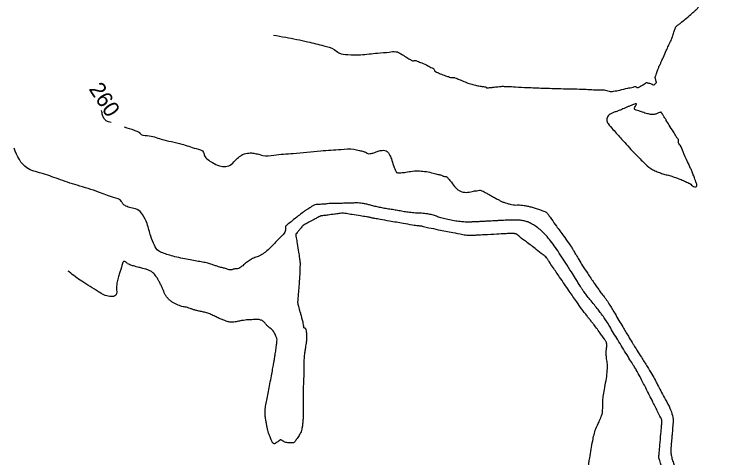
# Model space of a CAD drawing. Extents: x -478102 to -473059, y -1117705 to -1114104.
# Drawn here: x -475265.5 to -475088.2, y -1116409 to -1116297 of the extents above; entities that cross this region are included whole.
import ezdxf

# ---------------------------------------------------------------- set-up
doc = ezdxf.new("R2010")
doc.units = 0
for name, color, linetype in [('Vrstevnice_hlavni', 7, 'Continuous'), ('Vrstevnice_popis', 7, 'Continuous'), ('Vrstevnice_vedlejsi', 7, 'Continuous')]:
    doc.layers.add(name, color=color, linetype=linetype)

msp = doc.modelspace()

# ---------------------------------------------------------------- linework, layer by layer
at = {"layer": 'Vrstevnice_hlavni'}
for points in [[(-475240.975, -1116324.335), (-475242.24, -1116323.875), (-475242.75, -1116323.343), (-475243.137, -1116322.506), (-475243.415, -1116321.305)], [(-475237.687, -1116325.457), (-475235.201, -1116326.249), (-475234.334, -1116326.581), (-475233.844, -1116326.849), (-475233.73, -1116327.052), (-475231.91, -1116327.609), (-475228.384, -1116328.517), (-475223.153, -1116329.779), (-475219.586, -1116330.906), (-475217.681, -1116331.898), (-475217.44, -1116332.755), (-475216.694, -1116333.605), (-475215.441, -1116334.448), (-475213.683, -1116335.283), (-475212.092, -1116335.422), (-475210.667, -1116334.864), (-475209.409, -1116333.609), (-475208.319, -1116332.727), (-475207.397, -1116332.218), (-475206.642, -1116332.081), (-475205.948, -1116332.022), (-475205.314, -1116332.042), (-475204.739, -1116332.139), (-475204.122, -1116332.27), (-475203.462, -1116332.435), (-475202.76, -1116332.635), (-475199.972, -1116332.541), (-475195.097, -1116332.152), (-475188.137, -1116331.469), (-475183.035, -1116331.113), (-475179.791, -1116331.083), (-475178.406, -1116331.38), (-475177.36, -1116331.658), (-475176.654, -1116331.916), (-475176.288, -1116332.154), (-475175.662, -1116332.174), (-475174.776, -1116331.975), (-475173.631, -1116331.557), (-475172.686, -1116331.362), (-475171.941, -1116331.391), (-475171.397, -1116331.643), (-475170.862, -1116332.357), (-475170.337, -1116333.533), (-475169.822, -1116335.172), (-475169.381, -1116336.301), (-475169.015, -1116336.92), (-475168.725, -1116337.029), (-475167.953, -1116337.013), (-475166.701, -1116336.871), (-475164.969, -1116336.603), (-475163.238, -1116336.553), (-475161.509, -1116336.722), (-475159.783, -1116337.108), (-475158.522, -1116337.413), (-475157.729, -1116337.635), (-475157.401, -1116337.776), (-475157.09, -1116337.883), (-475156.795, -1116337.957), (-475156.517, -1116337.998), (-475155.978, -1116338.488), (-475155.178, -1116339.429), (-475154.117, -1116340.82), (-475152.888, -1116341.664), (-475151.489, -1116341.961), (-475149.92, -1116341.711), (-475148.805, -1116341.537), (-475148.141, -1116341.439), (-475147.93, -1116341.416), (-475147.518, -1116341.551), (-475146.905, -1116341.845), (-475146.091, -1116342.298), (-475145.239, -1116342.772), (-475144.347, -1116343.269), (-475143.416, -1116343.787), (-475142.747, -1116344.148), (-475142.34, -1116344.352), (-475142.195, -1116344.4), (-475141.824, -1116344.514), (-475141.227, -1116344.693), (-475140.403, -1116344.939), (-475139.648, -1116345.093), (-475138.96, -1116345.154), (-475138.341, -1116345.124), (-475137.645, -1116345.157), (-475136.873, -1116345.252), (-475136.023, -1116345.411), (-475135.095, -1116345.637), (-475134.087, -1116345.929), (-475132.999, -1116346.289), (-475132.178, -1116346.581), (-475131.622, -1116346.805), (-475131.332, -1116346.962), (-475131.076, -1116347.169), (-475130.854, -1116347.427), (-475130.666, -1116347.736), (-475129.952, -1116348.756), (-475128.712, -1116350.487)], [(-475128.712, -1116350.487), (-475126.947, -1116352.929), (-475125.688, -1116354.692), (-475124.936, -1116355.774), (-475124.689, -1116356.176), (-475124.297, -1116356.837), (-475123.761, -1116357.756), (-475123.079, -1116358.935), (-475122.099, -1116360.499), (-475120.82, -1116362.449), (-475119.242, -1116364.785), (-475118.059, -1116366.501), (-475117.27, -1116367.598), (-475116.877, -1116368.076), (-475116.545, -1116368.489), (-475116.273, -1116368.839), (-475116.062, -1116369.125), (-475115.278, -1116370.396), (-475113.922, -1116372.653), (-475111.992, -1116375.896), (-475110.564, -1116378.288), (-475109.637, -1116379.83), (-475109.21, -1116380.521), (-475108.43, -1116381.767), (-475107.298, -1116383.569), (-475105.813, -1116385.925), (-475104.633, -1116387.876), (-475103.758, -1116389.422), (-475103.189, -1116390.563), (-475102.425, -1116392.024), (-475101.465, -1116393.806), (-475100.311, -1116395.909), (-475099.582, -1116397.851), (-475099.279, -1116399.632), (-475099.401, -1116401.253), (-475099.506, -1116402.6), (-475099.594, -1116403.675), (-475099.665, -1116404.478), (-475099.736, -1116405.304), (-475099.806, -1116406.152), (-475099.875, -1116407.025), (-475099.8, -1116408.005), (-475099.581, -1116409.094), (-475099.218, -1116410.291), (-475098.892, -1116411.377), (-475098.603, -1116412.354), (-475098.351, -1116413.22), (-475097.9, -1116414.106), (-475097.251, -1116415.011), (-475096.403, -1116415.935), (-475095.646, -1116416.751), (-475094.98, -1116417.459), (-475094.404, -1116418.058), (-475093.929, -1116418.639), (-475093.553, -1116419.201), (-475093.277, -1116419.744), (-475092.975, -1116420.422), (-475092.648, -1116421.234), (-475092.295, -1116422.179), (-475091.967, -1116423.198), (-475091.665, -1116424.289), (-475091.387, -1116425.454), (-475091.154, -1116426.436), (-475090.963, -1116427.235), (-475090.817, -1116427.851), (-475090.546, -1116428.687), (-475090.149, -1116429.742), (-475089.629, -1116431.015), (-475089.217, -1116431.994), (-475088.916, -1116432.677), (-475088.723, -1116433.065), (-475088.302, -1116433.641), (-475087.651, -1116434.404), (-475086.771, -1116435.354), (-475086.194, -1116436.127), (-475085.92, -1116436.721), (-475085.947, -1116437.137), (-475085.918, -1116437.46), (-475085.832, -1116437.689), (-475085.689, -1116437.825), (-475085.536, -1116437.999), (-475085.372, -1116438.211), (-475085.197, -1116438.461), (-475084.597, -1116439.5), (-475083.572, -1116441.328), (-475082.121, -1116443.945), (-475080.77, -1116446.086), (-475079.518, -1116447.752), (-475078.365, -1116448.942), (-475077.137, -1116450.177), (-475075.834, -1116451.457), (-475073.077, -1116454.108)]]:
    msp.add_spline(points, degree=3, dxfattribs=at)
at = {"layer": 'Vrstevnice_vedlejsi'}
for points in [[(-475152.721, -1116313.661), (-475151.357, -1116314.246), (-475150.061, -1116314.693), (-475148.833, -1116315.001), (-475147.674, -1116315.17), (-475146.877, -1116315.315), (-475146.443, -1116315.435), (-475146.371, -1116315.529), (-475146.287, -1116315.587), (-475146.192, -1116315.607), (-475146.085, -1116315.59), (-475145.596, -1116315.533), (-475144.725, -1116315.437), (-475143.473, -1116315.301), (-475142.637, -1116315.211), (-475142.219, -1116315.166), (-475142.218, -1116315.166), (-475142.206, -1116315.17), (-475142.182, -1116315.178), (-475142.147, -1116315.19), (-475141.105, -1116315.248), (-475139.057, -1116315.354), (-475136.002, -1116315.506), (-475132.173, -1116315.649), (-475127.57, -1116315.784), (-475122.193, -1116315.91), (-475118.375, -1116316.064), (-475116.116, -1116316.247), (-475115.416, -1116316.458), (-475114.287, -1116316.433), (-475112.73, -1116316.171), (-475110.744, -1116315.673), (-475109.364, -1116315.398), (-475108.59, -1116315.346), (-475108.421, -1116315.516), (-475108.063, -1116315.468), (-475107.515, -1116315.202), (-475106.778, -1116314.719), (-475106.277, -1116314.398), (-475106.012, -1116314.238), (-475105.982, -1116314.241), (-475105.807, -1116314.286), (-475105.487, -1116314.376), (-475105.022, -1116314.509), (-475104.68, -1116314.635), (-475104.461, -1116314.755), (-475104.365, -1116314.869), (-475104.212, -1116314.865), (-475103.999, -1116314.744), (-475103.728, -1116314.505), (-475103.554, -1116314.331), (-475103.475, -1116314.222), (-475103.493, -1116314.177), (-475103.536, -1116314.024), (-475103.603, -1116313.762), (-475103.694, -1116313.392), (-475103.761, -1116313.134), (-475103.803, -1116312.989), (-475103.821, -1116312.956), (-475103.714, -1116312.609), (-475103.481, -1116311.95), (-475103.123, -1116310.977), (-475102.854, -1116310.276), (-475102.675, -1116309.845), (-475102.585, -1116309.685), (-475102.277, -1116309.02), (-475101.752, -1116307.85), (-475101.01, -1116306.174), (-475100.456, -1116304.958), (-475100.09, -1116304.201), (-475099.912, -1116303.903), (-475099.679, -1116303.318), (-475099.391, -1116302.445), (-475099.048, -1116301.284), (-475098.705, -1116300.441), (-475098.363, -1116299.917), (-475098.023, -1116299.71), (-475097.315, -1116299.162), (-475096.242, -1116298.274), (-475094.802, -1116297.044), (-475093.807, -1116296.183), (-475093.256, -1116295.69), (-475093.149, -1116295.565), (-475092.996, -1116295.294), (-475092.795, -1116294.877), (-475092.547, -1116294.315), (-475092.28, -1116293.874), (-475091.993, -1116293.556), (-475091.686, -1116293.36), (-475091.142, -1116293.181), (-475090.361, -1116293.019), (-475089.343, -1116292.873), (-475088.364, -1116292.639), (-475087.426, -1116292.318), (-475086.526, -1116291.909), (-475085.548, -1116291.453), (-475084.49, -1116290.949)], [(-475200.063, -1116302.278), (-475196.986, -1116302.839), (-475191.444, -1116303.945), (-475187.356, -1116304.971), (-475184.723, -1116305.915), (-475183.543, -1116306.779), (-475181.332, -1116307.215), (-475178.09, -1116307.223), (-475173.817, -1116306.804), (-475170.847, -1116306.551), (-475169.18, -1116306.463), (-475168.816, -1116306.541), (-475168.19, -1116306.843), (-475167.302, -1116307.368), (-475166.152, -1116308.116), (-475165.299, -1116308.583), (-475164.742, -1116308.77), (-475164.482, -1116308.675), (-475163.793, -1116308.85), (-475162.676, -1116309.296), (-475161.129, -1116310.012), (-475160.07, -1116310.578), (-475159.499, -1116310.995), (-475159.415, -1116311.262), (-475158.914, -1116311.607), (-475157.997, -1116312.03), (-475156.662, -1116312.532), (-475155.703, -1116312.855), (-475155.12, -1116313.001), (-475154.913, -1116312.969), (-475154.705, -1116312.963), (-475154.498, -1116312.983), (-475154.292, -1116313.03), (-475153.699, -1116313.256), (-475152.721, -1116313.661)], [(-475097.965, -1116328.589), (-475097.927, -1116328.981), (-475097.916, -1116329.121), (-475097.912, -1116329.205), (-475097.916, -1116329.233), (-475097.537, -1116330.084), (-475096.776, -1116331.757), (-475095.633, -1116334.251), (-475094.868, -1116335.923), (-475094.48, -1116336.771), (-475094.47, -1116336.797), (-475094.283, -1116337.295), (-475093.921, -1116338.265), (-475093.383, -1116339.709), (-475093.356, -1116340.466), (-475093.841, -1116340.538), (-475094.838, -1116339.924), (-475095.888, -1116339.363), (-475096.99, -1116338.856), (-475098.144, -1116338.403), (-475099.301, -1116338.002), (-475100.461, -1116337.651), (-475101.624, -1116337.351), (-475102.755, -1116336.968), (-475103.856, -1116336.5), (-475104.925, -1116335.949), (-475106.684, -1116334.435), (-475109.132, -1116331.959), (-475112.269, -1116328.522), (-475114.452, -1116326.075), (-475115.681, -1116324.618), (-475115.956, -1116324.153), (-475116.041, -1116323.672), (-475115.937, -1116323.177), (-475115.643, -1116322.668), (-475115.172, -1116322.236), (-475114.523, -1116321.881), (-475113.696, -1116321.603), (-475112.936, -1116321.324), (-475112.243, -1116321.044), (-475111.617, -1116320.763), (-475110.956, -1116320.478), (-475110.26, -1116320.187), (-475109.529, -1116319.892), (-475108.995, -1116319.692), (-475108.657, -1116319.588), (-475108.517, -1116319.58), (-475108.518, -1116319.724), (-475108.659, -1116320.019), (-475108.942, -1116320.467), (-475109.023, -1116320.812), (-475108.902, -1116321.054), (-475108.581, -1116321.193), (-475107.952, -1116321.417), (-475107.017, -1116321.727), (-475105.773, -1116322.123), (-475104.717, -1116322.301), (-475103.848, -1116322.261), (-475103.166, -1116322.002), (-475102.695, -1116321.817), (-475102.435, -1116321.704), (-475102.386, -1116321.664), (-475102.266, -1116321.788), (-475102.076, -1116322.074), (-475101.814, -1116322.523), (-475101.628, -1116322.845), (-475101.517, -1116323.039), (-475101.481, -1116323.106), (-475101.453, -1116323.152), (-475101.434, -1116323.178), (-475101.423, -1116323.185), (-475101.409, -1116323.194), (-475101.391, -1116323.208), (-475101.37, -1116323.225), (-475101, -1116323.81), (-475100.281, -1116324.963), (-475099.214, -1116326.685), (-475098.487, -1116327.847), (-475098.102, -1116328.449), (-475098.058, -1116328.492), (-475098.023, -1116328.526), (-475097.997, -1116328.552), (-475097.965, -1116328.589)], [(-475158.731, -1116348.111), (-475159.722, -1116347.73), (-475160.912, -1116347.451), (-475162.3, -1116347.275), (-475163.886, -1116347.201), (-475165.382, -1116347.074), (-475166.785, -1116346.895), (-475168.098, -1116346.663), (-475169.415, -1116346.436), (-475170.735, -1116346.214), (-475172.06, -1116345.996), (-475173.309, -1116345.754), (-475174.481, -1116345.488), (-475175.577, -1116345.197), (-475176.528, -1116344.968), (-475177.333, -1116344.801), (-475177.993, -1116344.696), (-475178.759, -1116344.641), (-475179.63, -1116344.636), (-475180.606, -1116344.682), (-475181.738, -1116344.715), (-475183.026, -1116344.736), (-475184.47, -1116344.745), (-475185.607, -1116344.776), (-475186.437, -1116344.827), (-475186.96, -1116344.9), (-475187.554, -1116344.953), (-475188.219, -1116344.986), (-475188.954, -1116344.999), (-475189.644, -1116345.147), (-475190.288, -1116345.431), (-475190.886, -1116345.85), (-475191.368, -1116346.174), (-475191.735, -1116346.403), (-475191.986, -1116346.536), (-475192.676, -1116347.039), (-475193.804, -1116347.91), (-475195.37, -1116349.15), (-475196.425, -1116349.99), (-475196.969, -1116350.431), (-475197.002, -1116350.471), (-475197.026, -1116350.667), (-475197.041, -1116351.02), (-475197.047, -1116351.53), (-475197.212, -1116352.028), (-475197.537, -1116352.515), (-475198.022, -1116352.991), (-475198.781, -1116353.764), (-475199.814, -1116354.835), (-475201.12, -1116356.204), (-475202.383, -1116357.259), (-475203.601, -1116357.999), (-475204.774, -1116358.424), (-475205.87, -1116358.977), (-475206.887, -1116359.66), (-475207.826, -1116360.471), (-475208.565, -1116361.005), (-475209.105, -1116361.262), (-475209.445, -1116361.241), (-475209.807, -1116361.275), (-475210.191, -1116361.363), (-475210.596, -1116361.506), (-475211.022, -1116361.538), (-475211.468, -1116361.459), (-475211.935, -1116361.269), (-475212.4, -1116361.113), (-475212.862, -1116360.991), (-475213.322, -1116360.903), (-475213.925, -1116360.731), (-475214.671, -1116360.473), (-475215.56, -1116360.132), (-475216.647, -1116359.827), (-475217.932, -1116359.56), (-475219.414, -1116359.329), (-475221.073, -1116359.024), (-475222.906, -1116358.645), (-475224.916, -1116358.191), (-475226.611, -1116357.719), (-475227.992, -1116357.23), (-475229.059, -1116356.723), (-475230.069, -1116355.322), (-475231.023, -1116353.029), (-475231.919, -1116349.842), (-475233.058, -1116347.587), (-475234.439, -1116346.264), (-475236.062, -1116345.872), (-475237.26, -1116345.405), (-475238.033, -1116344.861), (-475238.381, -1116344.242), (-475240.418, -1116343.253), (-475244.143, -1116341.897), (-475249.556, -1116340.172), (-475254.377, -1116338.582), (-475258.605, -1116337.127), (-475262.24, -1116335.808), (-475265.477, -1116330.842)], [(-475188.022, -1116347.916), (-475188.118, -1116347.918), (-475188.207, -1116347.937), (-475188.291, -1116347.974), (-475188.368, -1116348.028), (-475188.867, -1116348.302), (-475189.787, -1116348.796), (-475191.128, -1116349.509), (-475192.049, -1116350.005), (-475192.55, -1116350.286), (-475192.631, -1116350.35), (-475192.879, -1116350.629), (-475193.293, -1116351.123), (-475193.874, -1116351.832), (-475194.261, -1116352.309), (-475194.455, -1116352.554), (-475194.455, -1116352.568), (-475194.455, -1116352.589), (-475194.453, -1116352.616), (-475194.451, -1116352.65), (-475194.331, -1116353.402), (-475194.093, -1116354.873), (-475193.737, -1116357.062), (-475193.497, -1116358.62), (-475193.374, -1116359.547), (-475193.367, -1116359.843), (-475193.372, -1116360.37), (-475193.389, -1116361.128), (-475193.417, -1116362.116), (-475193.49, -1116363.448), (-475193.608, -1116365.123), (-475193.772, -1116367.141), (-475193.887, -1116368.581), (-475193.953, -1116369.442), (-475193.97, -1116369.725), (-475193.915, -1116370.149), (-475193.789, -1116370.715), (-475193.592, -1116371.423), (-475193.46, -1116371.896), (-475193.394, -1116372.135), (-475193.393, -1116372.139), (-475193.375, -1116372.184), (-475193.34, -1116372.269), (-475193.288, -1116372.395), (-475193.163, -1116372.836), (-475192.966, -1116373.594), (-475192.696, -1116374.668), (-475192.535, -1116375.417), (-475192.484, -1116375.841), (-475192.542, -1116375.94), (-475192.497, -1116376.03), (-475192.351, -1116376.11), (-475192.102, -1116376.181), (-475191.916, -1116376.537), (-475191.791, -1116377.179), (-475191.729, -1116378.108), (-475191.717, -1116378.896), (-475191.757, -1116379.544), (-475191.847, -1116380.052), (-475191.959, -1116380.768), (-475192.094, -1116381.693), (-475192.252, -1116382.826), (-475192.352, -1116383.918), (-475192.394, -1116384.97), (-475192.379, -1116385.98), (-475192.394, -1116387.165), (-475192.438, -1116388.525), (-475192.511, -1116390.058), (-475192.559, -1116391.582), (-475192.582, -1116393.096), (-475192.579, -1116394.6), (-475192.576, -1116395.902), (-475192.573, -1116397.002), (-475192.569, -1116397.901), (-475192.601, -1116398.849), (-475192.669, -1116399.846), (-475192.774, -1116400.892), (-475192.918, -1116401.742), (-475193.101, -1116402.397), (-475193.325, -1116402.857), (-475193.6, -1116403.337), (-475193.927, -1116403.838), (-475194.305, -1116404.359), (-475194.59, -1116404.741), (-475194.781, -1116404.983), (-475194.879, -1116405.086), (-475195.149, -1116405.151), (-475195.592, -1116405.177), (-475196.208, -1116405.165), (-475196.732, -1116405.095), (-475197.166, -1116404.967), (-475197.509, -1116404.782), (-475197.765, -1116404.64), (-475197.936, -1116404.543), (-475198.021, -1116404.489), (-475198.122, -1116404.455), (-475198.237, -1116404.44)], [(-475121.059, -1116414.567), (-475120.318, -1116408.958), (-475119.556, -1116404.64), (-475118.772, -1116401.612), (-475117.966, -1116399.876), (-475117.414, -1116398.553), (-475117.116, -1116397.642), (-475117.072, -1116397.145), (-475117.038, -1116396.462), (-475117.013, -1116395.595), (-475116.998, -1116394.542), (-475116.841, -1116393.075), (-475116.543, -1116391.194), (-475116.104, -1116388.899), (-475115.876, -1116386.929), (-475115.86, -1116385.286), (-475116.056, -1116383.969), (-475116.148, -1116382.808), (-475116.136, -1116381.804), (-475116.021, -1116380.955), (-475116.014, -1116380.276), (-475116.115, -1116379.766), (-475116.325, -1116379.426), (-475116.483, -1116379.17), (-475116.587, -1116378.999), (-475116.638, -1116378.913), (-475116.996, -1116378.416), (-475117.662, -1116377.508), (-475118.635, -1116376.189), (-475119.405, -1116375.162), (-475119.971, -1116374.429), (-475120.334, -1116373.989), (-475120.837, -1116373.349), (-475121.48, -1116372.51), (-475122.264, -1116371.471), (-475123.596, -1116369.596), (-475125.477, -1116366.885), (-475127.906, -1116363.338), (-475129.602, -1116360.851), (-475130.565, -1116359.425), (-475130.795, -1116359.058), (-475130.976, -1116358.776), (-475131.108, -1116358.576), (-475131.192, -1116358.46), (-475132.083, -1116357.735), (-475133.783, -1116356.399), (-475136.29, -1116354.453), (-475138.023, -1116353.135), (-475138.981, -1116352.446), (-475139.163, -1116352.384), (-475139.383, -1116352.344), (-475139.639, -1116352.325), (-475139.931, -1116352.327), (-475140.173, -1116352.332), (-475140.365, -1116352.338), (-475140.506, -1116352.347), (-475141.63, -1116352.407), (-475143.736, -1116352.52), (-475146.824, -1116352.685), (-475148.936, -1116352.799), (-475150.071, -1116352.86), (-475150.229, -1116352.87), (-475150.427, -1116352.877), (-475150.665, -1116352.881), (-475150.944, -1116352.882), (-475152.328, -1116352.647), (-475154.819, -1116352.176), (-475158.415, -1116351.47), (-475160.897, -1116350.966), (-475162.262, -1116350.666), (-475162.513, -1116350.57), (-475162.813, -1116350.5), (-475163.164, -1116350.455), (-475163.565, -1116350.436), (-475164.967, -1116350.223), (-475167.372, -1116349.816), (-475170.778, -1116349.215), (-475173.16, -1116348.796), (-475174.518, -1116348.559), (-475174.853, -1116348.504), (-475175.168, -1116348.443), (-475175.465, -1116348.376), (-475175.741, -1116348.302), (-475176.628, -1116348.142), (-475178.123, -1116347.893), (-475180.229, -1116347.557), (-475181.665, -1116347.335), (-475182.432, -1116347.226), (-475182.53, -1116347.231), (-475182.643, -1116347.234), (-475182.772, -1116347.236), (-475182.917, -1116347.237), (-475183.554, -1116347.313), (-475184.684, -1116347.464), (-475186.305, -1116347.689), (-475187.418, -1116347.84), (-475188.022, -1116347.916)], [(-475112.702, -1116440.792), (-475112.898, -1116440.773), (-475113.317, -1116440.758), (-475113.96, -1116440.747), (-475114.826, -1116440.739), (-475115.433, -1116440.736), (-475115.78, -1116440.738), (-475115.868, -1116440.743), (-475116.06, -1116440.759), (-475116.354, -1116440.786), (-475116.751, -1116440.823), (-475116.895, -1116440.781), (-475116.785, -1116440.662), (-475116.422, -1116440.463), (-475115.889, -1116440.293), (-475115.186, -1116440.15), (-475114.313, -1116440.034), (-475112.681, -1116437.423), (-475110.291, -1116432.317), (-475107.142, -1116424.715), (-475104.814, -1116419.098), (-475103.308, -1116415.465), (-475102.624, -1116413.816), (-475102.257, -1116412.408), (-475102.208, -1116411.242), (-475102.478, -1116410.316), (-475102.675, -1116409.643), (-475102.799, -1116409.22), (-475102.851, -1116409.049), (-475102.882, -1116408.894), (-475102.893, -1116408.754), (-475102.883, -1116408.63), (-475102.794, -1116407.614), (-475102.626, -1116405.706), (-475102.379, -1116402.907), (-475102.208, -1116400.964), (-475102.114, -1116399.877), (-475102.097, -1116399.646), (-475102.14, -1116399.392), (-475102.244, -1116399.114), (-475102.409, -1116398.814), (-475103.122, -1116397.406), (-475104.383, -1116394.889), (-475106.192, -1116391.263), (-475107.588, -1116388.546), (-475108.57, -1116386.736), (-475109.139, -1116385.834), (-475109.917, -1116384.586), (-475110.905, -1116382.992), (-475112.102, -1116381.052), (-475113.23, -1116379.204), (-475114.29, -1116377.448), (-475115.28, -1116375.783), (-475116.137, -1116374.406), (-475116.862, -1116373.317), (-475117.454, -1116372.514), (-475118.217, -1116371.532), (-475119.15, -1116370.371), (-475120.254, -1116369.031), (-475121.144, -1116367.91), (-475121.819, -1116367.009), (-475122.28, -1116366.327), (-475122.677, -1116365.717), (-475123.01, -1116365.179), (-475123.279, -1116364.713), (-475123.923, -1116363.663), (-475124.942, -1116362.029), (-475126.336, -1116359.81), (-475127.672, -1116357.767), (-475128.951, -1116355.9), (-475130.171, -1116354.208), (-475131.375, -1116352.777), (-475132.563, -1116351.608), (-475133.733, -1116350.699), (-475134.791, -1116350), (-475135.736, -1116349.511), (-475136.568, -1116349.231), (-475137.567, -1116349.048), (-475138.731, -1116348.961), (-475140.061, -1116348.971), (-475141.163, -1116348.991), (-475142.036, -1116349.02), (-475142.682, -1116349.059), (-475143.592, -1116349.11), (-475144.767, -1116349.175), (-475146.206, -1116349.252), (-475147.374, -1116349.316), (-475148.271, -1116349.367), (-475148.897, -1116349.406), (-475149.681, -1116349.433), (-475150.625, -1116349.448), (-475151.727, -1116349.453), (-475153.008, -1116349.349), (-475154.466, -1116349.136), (-475156.103, -1116348.814), (-475157.524, -1116348.473), (-475158.731, -1116348.111)], [(-475236.858, -1116359.958), (-475237.06, -1116359.737), (-475237.278, -1116359.565), (-475237.512, -1116359.444), (-475237.762, -1116359.371), (-475237.974, -1116359.516), (-475238.149, -1116359.877), (-475238.285, -1116360.455), (-475238.498, -1116361.198), (-475238.789, -1116362.107), (-475239.157, -1116363.182), (-475239.445, -1116364.507), (-475239.652, -1116366.083), (-475239.779, -1116367.911), (-475241.284, -1116368.236), (-475244.166, -1116367.06), (-475248.426, -1116364.381), (-475251.559, -1116362.054), (-475251.817, -1116361.843)], [(-475198.237, -1116404.44), (-475198.369, -1116404.444), (-475198.465, -1116404.465), (-475198.525, -1116404.502), (-475198.551, -1116404.557), (-475198.698, -1116404.685), (-475198.967, -1116404.889), (-475199.358, -1116405.166), (-475199.676, -1116405.332), (-475199.92, -1116405.387), (-475200.091, -1116405.331), (-475200.239, -1116405.206), (-475200.365, -1116405.014), (-475200.47, -1116404.754), (-475200.62, -1116404.388), (-475200.815, -1116403.918), (-475201.056, -1116403.343), (-475201.277, -1116402.696), (-475201.478, -1116401.977), (-475201.659, -1116401.185), (-475201.833, -1116400.299), (-475202, -1116399.317), (-475202.161, -1116398.241), (-475202.159, -1116396.99), (-475201.994, -1116395.565), (-475201.667, -1116393.964), (-475201.321, -1116392.206), (-475200.957, -1116390.29), (-475200.574, -1116388.215), (-475200.266, -1116386.54), (-475200.032, -1116385.263), (-475199.872, -1116384.386), (-475199.697, -1116383.316), (-475199.508, -1116382.054), (-475199.304, -1116380.6), (-475199.196, -1116379.537), (-475199.184, -1116378.867), (-475199.268, -1116378.587), (-475199.428, -1116378.211), (-475199.666, -1116377.739), (-475199.98, -1116377.171), (-475200.314, -1116376.716), (-475200.669, -1116376.373), (-475201.045, -1116376.143), (-475201.47, -1116375.781), (-475201.943, -1116375.287), (-475202.466, -1116374.661), (-475203.109, -1116374.248), (-475203.873, -1116374.048), (-475204.757, -1116374.062), (-475205.547, -1116374.084), (-475206.243, -1116374.116), (-475206.845, -1116374.156), (-475207.632, -1116374.258), (-475208.603, -1116374.422), (-475209.76, -1116374.647), (-475210.807, -1116374.692), (-475211.745, -1116374.559), (-475212.573, -1116374.245), (-475213.49, -1116373.859), (-475214.496, -1116373.402), (-475215.59, -1116372.872), (-475216.653, -1116372.454), (-475217.687, -1116372.15), (-475218.691, -1116371.958), (-475219.591, -1116371.744), (-475220.388, -1116371.509), (-475221.082, -1116371.252), (-475221.724, -1116371.049), (-475222.316, -1116370.899), (-475222.856, -1116370.804), (-475223.449, -1116370.644), (-475224.095, -1116370.419), (-475224.793, -1116370.13), (-475225.45, -1116369.757), (-475226.068, -1116369.3), (-475226.644, -1116368.76), (-475227.125, -1116368.157), (-475227.509, -1116367.492), (-475227.796, -1116366.764), (-475228.129, -1116365.999), (-475228.509, -1116365.198), (-475228.934, -1116364.361), (-475229.337, -1116363.651), (-475229.719, -1116363.07), (-475230.079, -1116362.617), (-475230.45, -1116362.243), (-475230.83, -1116361.948), (-475231.221, -1116361.732), (-475231.601, -1116361.557), (-475231.97, -1116361.423), (-475232.328, -1116361.331), (-475233.007, -1116361.152), (-475234.009, -1116360.885), (-475235.333, -1116360.532), (-475236.282, -1116360.223), (-475236.858, -1116359.958)]]:
    msp.add_spline(points, degree=3, dxfattribs=at)

# ---------------------------------------------------------------- texts
at = {"layer": 'Vrstevnice_popis'}
msp.add_text(' 260 ', height=4, rotation=303.2134, dxfattribs=at).set_placement((-475247.575, -1116314.62))

doc.saveas('drawing.dxf')
